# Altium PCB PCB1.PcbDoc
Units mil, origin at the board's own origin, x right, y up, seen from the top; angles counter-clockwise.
Board outline 1660 x 815 mil, 2 copper layers (L1, L2), stack 62.8 mil thick; 14 components, 14 nets, 70 pads, 2 vias.
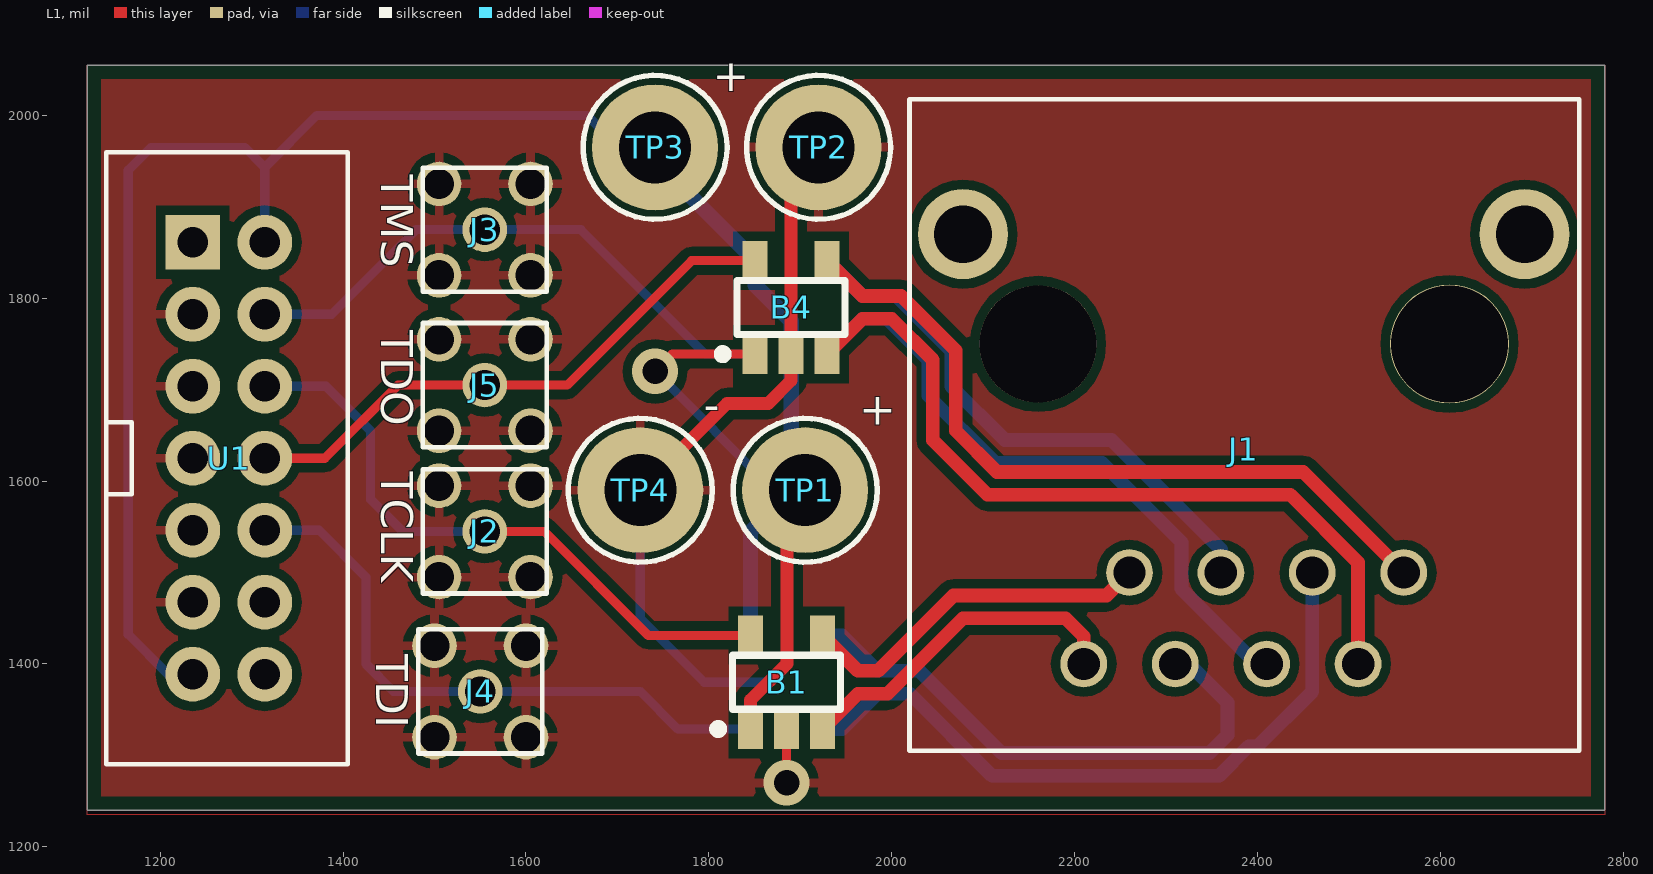
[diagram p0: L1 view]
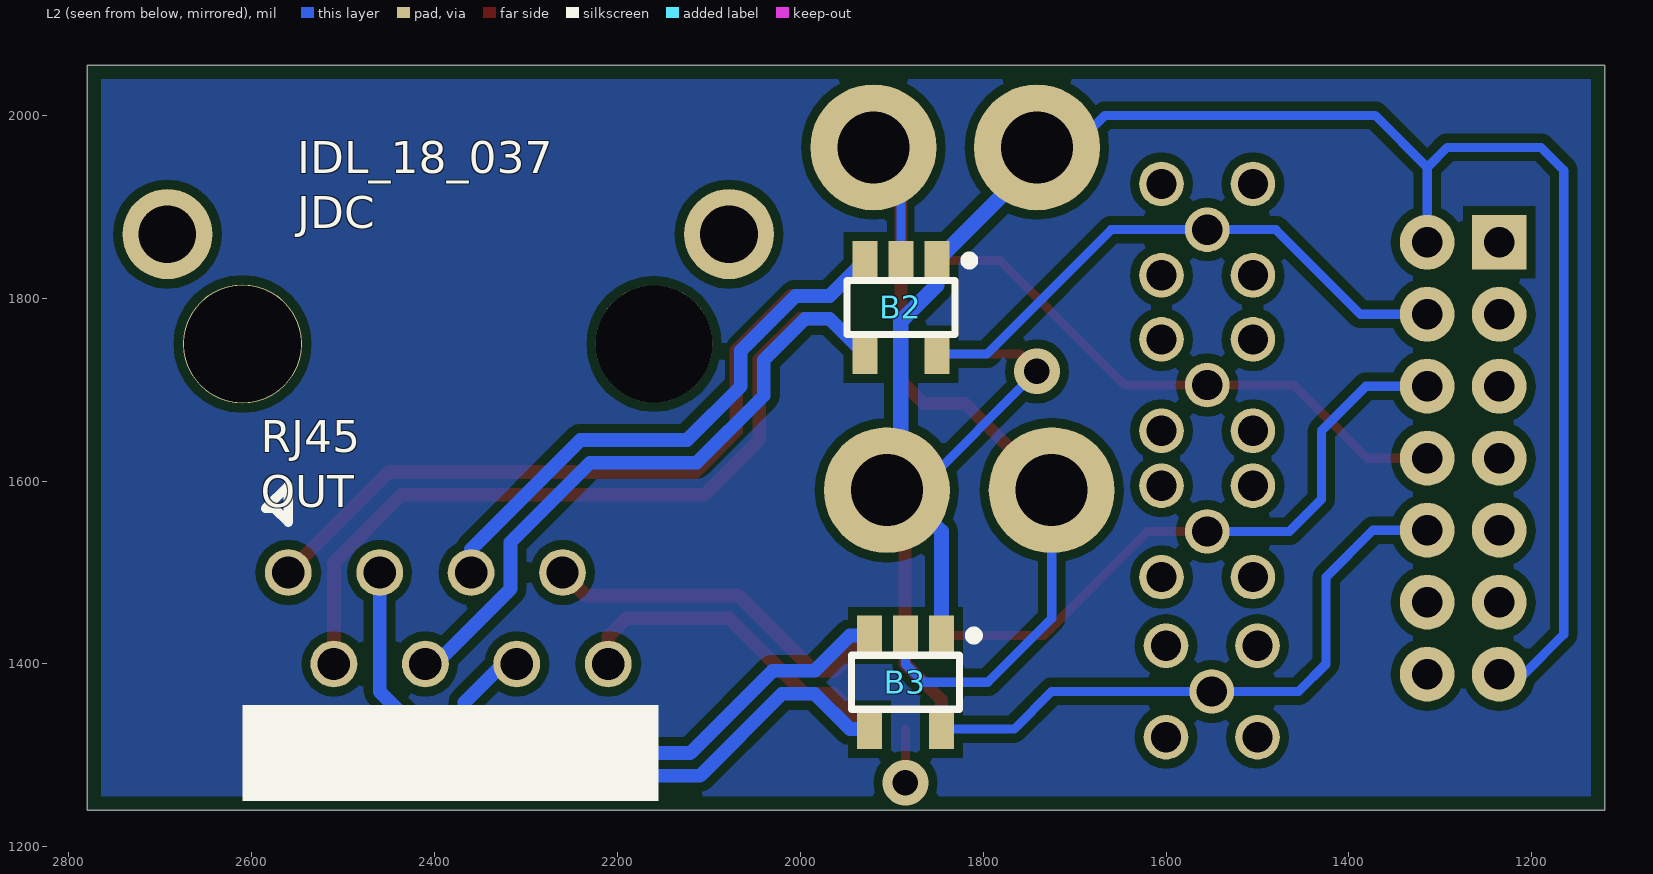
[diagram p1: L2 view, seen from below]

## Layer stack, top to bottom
Top Solder: solder mask 0.1, Solder Resist, Dk 0
L1: signal copper 1.4
Core: dielectric 60, FR-4, Dk 4.6
L2: signal copper 1.4
Bottom Solder: solder mask 0.1, Solder Resist, Dk 0

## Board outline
1120,1240 1120,2055 2780,2055 2780,1240

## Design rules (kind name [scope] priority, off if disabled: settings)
BoardOutlineClearance [All] p1: gap=15 ignorepadtopadclearanceinfootprint=FALSE
Clearance [All] p1: gap=10 ignorepadtopadclearanceinfootprint=FALSE except(0: Arc-Hole Track-Hole SMDPad-Hole THPad-Hole Via-Hole Fill-Hole Poly-Hole Region-Hole Text-Hole)
DiffPairsRouting [All] p1: maxlimit=10 minlimit=10 mostfreqgap=10 toplayer_minwidth=15 toplayer_maxwidth=15 toplayer_prefwidth=15 bottomlayer_minwidth=15 bottomlayer_maxwidth=15 bottomlayer_prefwidth=15 maxuncoupledlength=500
PolygonConnect [All] p1: connectstyle=Relief reliefconductorwidth=10 reliefentries=4 polygonreliefangle="90 Angle" airgapwidth=10
RoomDefinition Sheet1 [InComponentClass('Sheet1')] p1: confinementstyle=ConfineIn formatcopy=TRUE lockcomponents=FALSE outline 7045,1060 10420,1060 10420,2525 7045,2525
RoutingVias [All] p1: holewidth=28 width=50 viastyle="Through Hole" minholewidth=28 minwidth=50 maxholewidth=28 maxwidth=50
SolderMaskExpansion [All] p1: expansion=4
Width [All] p1: maxlimit=10 minlimit=10 preferedwidth=10
29 further rules are at their usual default settings.

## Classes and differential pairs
differential pair TMS1: +TMS1_P -TMS1_N
differential pair TDO1: +TDO1_P -TDO1_N
differential pair TDI1: +TDI1_P -TDI1_N
differential pair TCK1: +TCK1_P -TCK1_N

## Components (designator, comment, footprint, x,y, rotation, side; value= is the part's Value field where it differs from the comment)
B1 "SN65LVDS1DBVR(LVTTL-LVDS)" SOT23_5PIN 1885,1380 r90 top
B2 "SN65LVDS1DBVR(LVTTL-LVDS)" SOT23_5PIN 1890,1790 r270 bottom
B3 "SN65LVDS1DBVR(LVTTL-LVDS)" SOT23_5PIN 1885,1380 r270 bottom
B4 "SN65LVDT2DBVR(LVDS-LVTTL)" SOT23_5PIN 1890,1790 r90 top
J1 "0855085001" "VIRT RJ45" 2610,1750 r180 top
J2 "MMCX" MMCX_VERTICAL_THROUGH_HOLE 1555,1545 r0 top
J3 "MMCX" MMCX_VERTICAL_THROUGH_HOLE 1555,1875 r0 top
J4 "MMCX" MMCX_VERTICAL_THROUGH_HOLE 1550,1370 r0 top
J5 "MMCX" MMCX_VERTICAL_THROUGH_HOLE 1555,1705 r0 top
TP1 "TP 0.5mm" SP2.0 1905.36,1590 r180 top
TP2 "TP 2.0mm" SP2.0 1920,1965 r0 top
TP3 "TP 0.5mm" SP2.0 1741.18,1965 r0 top
TP4 "TP 0.5mm" SP2.0 1725,1590 r0 top
U1 "JTAG 14PIN" JTAG_14PIN_2MM_VERT 1275,1625 r270 top

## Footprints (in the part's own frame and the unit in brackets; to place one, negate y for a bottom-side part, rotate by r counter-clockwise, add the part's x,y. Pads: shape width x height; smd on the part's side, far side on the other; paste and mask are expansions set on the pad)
JTAG_14PIN_2MM_VERT [mil]
  rect 60x60 hole 33: 1(-236.22,-39.37)
  round 60 hole 33: 2(-236.22,39.37) 3(-157.48,-39.37) 4(-157.48,39.37) 5(-78.74,-39.37) 6(-78.74,39.37) 7(0,-39.37) 8(0,39.37) 9(78.74,-39.37) 10(78.74,39.37) 11(157.48,-39.37) 12(157.48,39.37) 13(236.22,-39.37) 14(236.22,39.37)
  silkscreen extent -335,-134 335,130, body extent -328,-124 328,124, height 254
MMCX_VERTICAL_THROUGH_HOLE [mm]
  round 1.24 hole 0.84: 1(0,0) 2(-1.27,-1.27) 3(1.27,-1.27) 4(1.27,1.27) 5(-1.27,1.27)
  silkscreen extent -1.73,-1.73 1.73,1.73, body extent -1.73,-1.73 1.73,1.73, height 4.42
SOT23_5PIN [mm] "SOT23, 5-Leads, Body 3.00x2.80mm, Pitch 1.00mm, IPC Medium Density"
  rect 1.1x0.7 smd: 1(-1.3,1) 2(-1.3,0) 3(-1.3,-1) 4(1.3,-1) 5(1.3,1)
  silkscreen extent -1.42,-1.5 0.75,2.02, body extent -0.75,-1.5 0.75,1.5, height 1
SP2.0 [mm] "Solder Pin 2.0mm"
  round 3.5 hole 2: 1(0,0)
  silkscreen extent -2,-2 2,2
"VIRT RJ45" [mm] "Single_Verticle_RJ-45"
  round 1.3 hole 0.9: A1(1.27,6.35) A2(2.54,8.89) A3(3.81,6.35) A4(5.08,8.89) A5(6.35,6.35) A6(7.62,8.89) A7(8.89,6.35) A8(10.16,8.89)
  round 3.302 hole 3.25 unplated: M1(0,0)
  round 3.25 hole 3.25 unplated: M2(11.43,0)
  round 2.5 hole 1.6: M3(-2.085,-3.05) M4(13.515,-3.05)
  silkscreen extent -3.6,-6.8 15,11.3, body extent -2.6,-6.4 14,10.9, height 16.5

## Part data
B1 B2 B3: "IC HIGH DIFF LINE DRIVER SOT23-5", Manufacturer="Texas Instruments", Manufacturer #=SN65LVDS1DBVR, Package size=SOT-23-5, Supplier Part Number 1=296-6919-1-ND
B4: "IC DIFF LINE RECEIVER SOT-23-5", Manufacturer="Texas Instruments", Manufacturer #=SN65LVDT2DBVR, Package size=SOT-23-5, Supplier Part Number 1=296-6896-1-ND
J1: library part "VIRT RJ45 CONN", "CONN MOD JACK 8P8C R/A SHIELDED", Manufacturer="Molex, LLC", Package="8p8c virt", Supplier Part Number 1=WM4590-ND
J2 J3 J4 J5: "CONN MMCX JACK STR 50 OHM PCB", Manufacturer="Molex, LLC", Manufacturer part #=0734151471, Supplier Part Number 1=WM5557-ND
TP1 TP2 TP3 TP4: library part ELE-TP0.5S, "Test Point 0.5mm Slim"
U1: "CONN HEADER 14POS 2MM GOLD DIP", Manufacturer="Hirose Electric Co Ltd", Manufacturer part #=A3C-14P-2DSA, Package size="14 PIN 2MM PITCH", Supplier Part Number 1=H1813-ND

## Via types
v1: diameter 50, hole 28, L1 to L2, 2 vias

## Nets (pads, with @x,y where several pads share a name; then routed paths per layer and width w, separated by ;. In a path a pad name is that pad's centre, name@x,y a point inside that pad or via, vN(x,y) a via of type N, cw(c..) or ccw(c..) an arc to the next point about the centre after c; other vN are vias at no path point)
GND: B1.2 B2.2 B3.2 B4.2 J2.2 J2.3 J2.4 J2.5 J3.2 J3.3 J3.4 J3.5 J4.2 J4.3 J4.4 J4.5 J5.2 J5.3 J5.4 J5.5 TP2.1 TP4.1 U1.3 U1.5 U1.7 U1.9 U1.11 | length 1045.7
  L1 w10: v1(1885,1270) B1.2 ; TP2.1@1890,1935 TP2.1
  L1 w14: TP4.1 1820,1685 1865,1685 1890,1710 B4.2 TP2.1@1890,1935
  L2 w10: TP4.1 1725,1450 1795,1380 1865,1380 1885,1400 B3.2 ; B2.2 1890,1935 TP2.1
TCK1_N: B1.3 J1.A8 | length 374.1
  L1 w15: B1.3 1963.05,1367.5 1995.36,1367.5 2077.86,1450 2190,1450 2210,1430 J1.A8
TCK1_P: B1.4 J1.A7 | length 396.2
  L1 w15: B1.4 1963.05,1392.5 1985,1392.5 2067.5,1475 2235,1475 J1.A7
TCLK: B1.5 J2.1 U1.6 | length 678.1
  L1 w10: J2.1 1620,1545 1733.82,1431.18 B1.5
  L2 w10: U1.6@1324.37,1703.74 1381.26,1703.74 1430,1655 1430,1580 1465,1545 J2.1
TDI: B3.5 J4.1 U1.10 | length 667
  L2 w10: U1.10@1324.37,1546.26 1373.74,1546.26 1425,1495 1425,1400 1455,1370 J4.1 1725,1370 1766.18,1328.82 B3.5
TDI1_N: B3.3 J1.A6 | length 614.4
  L2 w15: B3.3 1945.65,1431.18 1984.33,1392.5 2030.36,1392.5 2120.21,1302.65 2347.65,1302.65 2367.16,1322.16 2367.16,1357.84 2325,1400 J1.A6
TDI1_P: B3.4 J1.A3 | length 757.1
  L2 w15: B3.4 1945.65,1328.82 1984.33,1367.5 2020,1367.5 2109.85,1277.65 2358,1277.65 2390.36,1310 2400.01,1310 2460,1369.99 J1.A3
TDO: B4.5 J5.1 U1.8 | length 625.8
  L1 w10: U1.8 1380,1625 1460,1705 J5.1 1645,1705 1781.18,1841.18 B4.5
TDO1_N: B4.3 J1.A2 | length 869.5
  L1 w15: B4.3 1968.05,1777.5 2000,1777.5 2045,1732.5 2045,1644.64 2104.64,1585 2435.94,1585 2510,1510.94 J1.A2
TDO1_P: B4.4 J1.A1 | length 823.4
  L1 w15: B4.4 1968.05,1802.5 2010.36,1802.5 2070,1742.86 2070,1655 2115,1610 2450,1610 J1.A1
TMS: B2.5 J3.1 U1.4 | length 621
  L2 w10: U1.4@1324.37,1782.48 1387.48,1782.48 1480,1875 J3.1 1660,1875 1796.18,1738.82 B2.5
TMS1_N: B2.3 J1.A5 | length 609.7
  L2 w15: B2.3 1968.05,1802.5 2005.36,1802.5 2065,1742.86 2065,1703.74 2123.74,1645 2240.36,1645 2360,1525.36 J1.A5
TMS1_P: B2.4 J1.A4 | length 705.8
  L2 w15: B2.4 1968.05,1777.5 1995,1777.5 2040,1732.5 2040,1693.39 2113.39,1620 2230,1620 2316.91,1533.09 2316.91,1482.15 2399.06,1400 J1.A4
VCC: B1.1 B2.1 B3.1 B4.1 TP1.1 TP3.1 U1.2 U1.13 | length 2533.6
  L1 w10: v1(1741.18,1720) 1760,1738.82 B4.1
  L1 w14: B1.1 1845.63,1360.63 1885.36,1400.36 TP1.1@1885.36,1585
  L2 w10: U1.13 1208.57,1388.78 1165,1432.35 1165,1940 1190,1965 1292.35,1965 1314.37,1942.98 ; U1.2 1314.37,1942.98 ; v1(1741.18,1720) 1871.18,1590 1890,1590 TP1.1 ; TP3.1@1741.18,1950.63 TP3.1 1701.76,1965 1666.76,2000 1371.39,2000 1314.37,1942.98
  L2 w16: B3.1 1845.63,1545.27 TP1.1@1890,1589.64
  L2 w17: TP3.1@1741.18,1950.63 B2.1 1850.63,1814.37 1890,1775 1890,1590 TP1.1@1890,1589.64
pads on no net: J1.M1 J1.M2 J1.M3 J1.M4 U1.1 U1.12 U1.14

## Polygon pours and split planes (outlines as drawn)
no net on L1 "L1-No Net" (solid, pour order 2): 1120,1235 1120,2055 2780,2055 2780,1235
GND on L1 "L1-GND" (solid, pour order 0): 1120,1235 1120,2055 2780,2055 2780,1235
no net on Bottom Overlay (solid): 2120,1340
no net on L2 "L2-No Net" (solid, pour order 4): 1120,1235 1120,2055 2780,2055 2780,1235

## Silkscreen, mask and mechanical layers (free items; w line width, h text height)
Top Overlay:
  text "+" at 1804.53,2015 h60
  text "TMS" at 1430,1934.84 h60 r270
  text "TDO" at 1430,1764.84 h60 r270
  text "-" at 1794.53,1655 h60
  text "+" at 1964.53,1650 h60
  text "TCLK" at 1430,1610.47 h60 r270
  text "TDI" at 1425,1410.47 h60 r270
Bottom Overlay:
  rectangle: 2155,1250 2610,1355
  lines w10: 2560,1555 2575,1570 2585,1570 2560,1595 2560,1555
  text "IDL_18_037 / JDC" at 2550,1865 h60
  text "RJ45 / OUT" at 2590,1560 h60
Mechanical 1:
  the board outline again, w10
